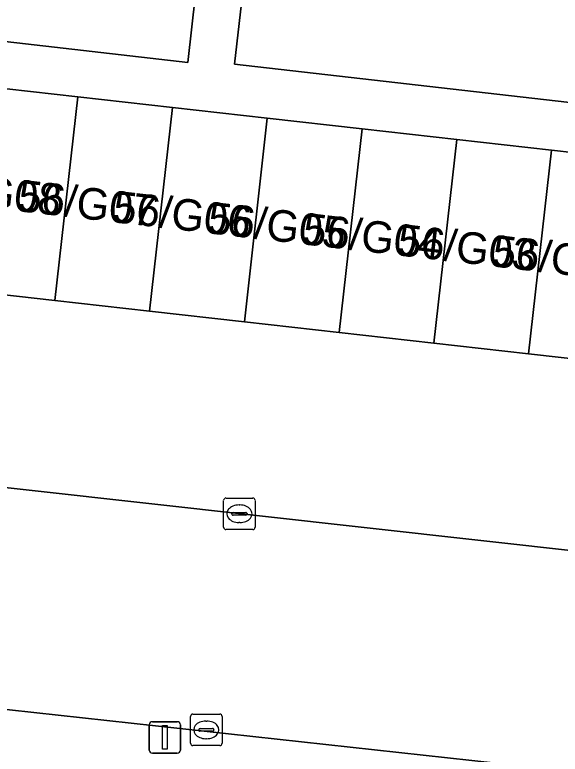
# Model space of a CAD drawing. Extents: x 161928 to 163071, y 386474 to 387428.
# Drawn here: x 162222.43 to 162239.74, y 386567.43 to 386590.88 of the extents above; entities that cross this region are included whole.
import ezdxf

# ---------------------------------------------------------------- set-up
doc = ezdxf.new("R2010")
doc.units = 0
for name, color, linetype in [('IMGEO_Erf', 7, 'Continuous'), ('IMGEO_Kolk', 7, 'Continuous'), ('IMGEO_Lichtmast', 7, 'Continuous'), ('IMGEO_Pand', 7, 'Continuous'), ('IMGEO_Pand_nummerreeks', 7, 'Continuous'), ('IMGEO_Rijbaan_lokaal_open', 7, 'Continuous'), ('IMGEO_Voetpad_open', 7, 'Continuous')]:
    doc.layers.add(name, color=color, linetype=linetype)

msp = doc.modelspace()

# ---------------------------------------------------------------- linework, layer by layer
at = {"layer": 'IMGEO_Erf'}
msp.add_lwpolyline([(162243.089, 386612.25), (162243.777, 386618.25), (162244.444, 386624.056), (162242.204, 386624.313), (162242.895, 386630.333), (162245.134, 386630.076), (162245.175, 386630.43), (162237.23, 386631.5), (162234.532, 386631.792), (162234.28, 386631.819), (162230.744, 386601.024), (162229.401, 386589.321), (162240.316, 386588.068), (162241.024, 386594.248), (162241.713, 386600.249), (162242.401, 386606.249)], close=True, dxfattribs=at)
msp.add_lwpolyline([(162222.049, 386626.7), (162221.352, 386620.648), (162220.657, 386614.617), (162219.964, 386608.612), (162219.27, 386602.591), (162218.588, 386596.675), (162217.88, 386590.526), (162227.916, 386589.37), (162228.16, 386591.548), (162225.844, 386591.807), (162226.29, 386595.787), (162226.733, 386599.742), (162229.232, 386599.462), (162229.7, 386603.636), (162227.201, 386603.916), (162227.633, 386607.77), (162228.08, 386611.753), (162230.578, 386611.473), (162231.038, 386615.572), (162228.598, 386615.846), (162229.038, 386619.772), (162229.484, 386623.756), (162231.925, 386623.482), (162232.4, 386627.717)], dxfattribs=at)
at = {"layer": 'IMGEO_Kolk'}
for p, q in [((162229.056, 386574.632), (162229.056, 386575.484)), ((162229.131, 386575.558), (162229.983, 386575.558)), ((162230.057, 386575.484), (162230.057, 386574.632)), ((162229.544, 386575.338), (162229.569, 386575.338)), ((162229.315, 386575.052), (162229.315, 386575.064)), ((162229.753, 386575.015), (162229.355, 386575.015)), ((162229.358, 386575.101), (162229.756, 386575.101)), ((162229.799, 386575.064), (162229.799, 386575.052)), ((162229.567, 386574.778), (162229.542, 386574.778)), ((162229.983, 386574.558), (162229.131, 386574.558)), ((162228.08, 386568.705), (162228.932, 386568.705)), ((162228.005, 386567.779), (162228.005, 386568.631)), ((162228.493, 386568.485), (162228.518, 386568.485)), ((162229.006, 386568.631), (162229.006, 386567.779)), ((162228.264, 386568.199), (162228.264, 386568.211)), ((162228.307, 386568.248), (162228.705, 386568.248)), ((162228.748, 386568.211), (162228.748, 386568.199)), ((162228.702, 386568.162), (162228.304, 386568.162)), ((162228.516, 386567.925), (162228.491, 386567.925)), ((162228.932, 386567.705), (162228.08, 386567.705))]:
    msp.add_line(p, q, dxfattribs=at)
for points in [[(162229.056, 386574.632), (162229.056, 386575.484)], [(162229.131, 386575.558), (162229.983, 386575.558)], [(162230.057, 386575.484), (162230.057, 386574.632)], [(162229.983, 386574.558), (162229.131, 386574.558)], [(162228.08, 386568.705), (162228.932, 386568.705)], [(162228.005, 386567.779), (162228.005, 386568.631)], [(162229.006, 386568.631), (162229.006, 386567.779)], [(162228.932, 386567.705), (162228.08, 386567.705)]]:
    msp.add_lwpolyline(points, dxfattribs=at)
for centre, radius, start, end in [((162229.133, 386575.482), 0.0765, 91.552, 178.448), ((162229.133, 386575.482), 0.0765, 91.552, 178.448), ((162229.981, 386575.482), 0.0765, 1.552, 88.448), ((162229.981, 386575.482), 0.0765, 1.552, 88.448), ((162229.355, 386575.061), 0.0403, 85.8775, 175.7526), ((162229.352, 386575.051), 0.0366, 178.938, 274.7102), ((162229.756, 386575.058), 0.043, 264.8664, 352.4533), ((162229.76, 386575.063), 0.0386, 1.7309, 96.639), ((162229.133, 386574.634), 0.0765, 181.552, 268.448), ((162229.133, 386574.634), 0.0765, 181.552, 268.448), ((162229.981, 386574.634), 0.0765, 271.552, 358.448), ((162229.981, 386574.634), 0.0765, 271.552, 358.448), ((162228.082, 386568.629), 0.0765, 91.552, 178.448), ((162228.082, 386568.629), 0.0765, 91.552, 178.448), ((162228.93, 386568.629), 0.0765, 1.552, 88.448), ((162228.93, 386568.629), 0.0765, 1.552, 88.448), ((162228.304, 386568.208), 0.0403, 85.8775, 175.7526), ((162228.709, 386568.21), 0.0386, 1.7309, 96.639), ((162228.301, 386568.198), 0.0366, 178.938, 274.7102), ((162228.705, 386568.205), 0.043, 264.8664, 352.4533), ((162228.082, 386567.781), 0.0765, 181.552, 268.448), ((162228.082, 386567.781), 0.0765, 181.552, 268.448), ((162228.93, 386567.781), 0.0765, 271.552, 358.448), ((162228.93, 386567.781), 0.0765, 271.552, 358.448)]:
    msp.add_arc(centre, radius, start, end, dxfattribs=at)
for centre, major_axis, ratio, start_param, end_param in [((162229.543, 386575.058), (-0.387, 0.002), 0.722429, 4.712389, 7.853982), ((162229.568, 386575.058), (-0.39, 0.002), 0.717154, 1.570796, 4.712389), ((162228.492, 386568.205), (-0.387, 0.002), 0.722429, 4.712389, 7.853982), ((162228.517, 386568.205), (-0.39, 0.002), 0.717154, 1.570796, 4.712389)]:
    msp.add_ellipse(centre, major_axis=major_axis, ratio=ratio, start_param=start_param, end_param=end_param, dxfattribs=at)
at = {"layer": 'IMGEO_Lichtmast'}
for p, q in [((162226.795, 386568.464), (162227.585, 386568.464)), ((162227.585, 386568.464), (162226.795, 386568.464)), ((162226.695, 386567.564), (162226.695, 386568.364)), ((162226.695, 386568.364), (162226.695, 386567.564)), ((162227.685, 386568.364), (162227.685, 386567.564)), ((162227.685, 386567.564), (162227.685, 386568.364)), ((162227.585, 386567.464), (162226.795, 386567.464)), ((162226.795, 386567.464), (162227.585, 386567.464))]:
    msp.add_line(p, q, dxfattribs=at)
msp.add_lwpolyline([(162227.115, 386568.339), (162227.265, 386568.339), (162227.265, 386567.589), (162227.115, 386567.589), (162227.115, 386568.339)], dxfattribs=at)
for centre, start, end in [((162226.795, 386568.364), 90, 180), ((162226.795, 386568.364), 90, 180), ((162227.585, 386568.364), 0, 90), ((162227.585, 386568.364), 360, 90), ((162226.795, 386567.564), 180, 270), ((162226.795, 386567.564), 180, 270), ((162227.585, 386567.564), 270, 0), ((162227.585, 386567.564), 270, 0)]:
    msp.add_arc(centre, 0.1, start, end, dxfattribs=at)
at = {"layer": 'IMGEO_Pand'}
for points in [[(162223.699, 386581.825), (162224.426, 386588.28), (162221.419, 386588.619), (162220.692, 386582.164)], [(162226.707, 386581.487), (162227.433, 386587.942), (162224.426, 386588.28), (162223.699, 386581.825)], [(162229.714, 386581.148), (162230.441, 386587.603), (162227.433, 386587.942), (162226.707, 386581.487)], [(162232.721, 386580.81), (162233.448, 386587.265), (162230.441, 386587.603), (162229.714, 386581.148)], [(162235.728, 386580.471), (162236.455, 386586.926), (162233.448, 386587.265), (162232.721, 386580.81)], [(162238.735, 386580.132), (162239.462, 386586.587), (162236.455, 386586.926), (162235.728, 386580.471)], [(162241.742, 386579.794), (162242.469, 386586.249), (162239.462, 386586.587), (162238.735, 386580.132)]]:
    msp.add_lwpolyline(points, close=True, dxfattribs=at)
at = {"layer": 'IMGEO_Rijbaan_lokaal_open'}
msp.add_lwpolyline([(162253.921, 386565.373), (162259.408, 386564.757), (162261.164, 386564.56), (162261.912, 386571.45), (162256.384, 386572.068), (162250.613, 386572.714), (162244.143, 386573.437), (162208.921, 386577.363), (162207.377, 386577.546), (162206.668, 386570.539), (162216.075, 386569.522)], close=True, dxfattribs=at)
at = {"layer": 'IMGEO_Voetpad_open'}
for points in [[(162240.316, 386588.068), (162229.401, 386589.321), (162230.744, 386601.024), (162234.28, 386631.819), (162234.532, 386631.792), (162237.23, 386631.5), (162245.175, 386630.43)], [(162204.829, 386592.006), (162204.672, 386590.589), (162212.398, 386589.635), (162215.405, 386589.296), (162218.412, 386588.958), (162221.419, 386588.619), (162224.426, 386588.28), (162227.433, 386587.942), (162230.441, 386587.603), (162233.448, 386587.265), (162236.455, 386586.926), (162239.462, 386586.587), (162242.469, 386586.249)], [(162228.16, 386591.548), (162227.916, 386589.37), (162217.88, 386590.526), (162214.92, 386590.867), (162209.952, 386591.44)], [(162208.921, 386577.363), (162244.143, 386573.437), (162244.508, 386576.484), (162244.749, 386579.455), (162241.742, 386579.794), (162238.735, 386580.132), (162235.728, 386580.471), (162232.721, 386580.81), (162229.714, 386581.148), (162226.707, 386581.487), (162223.699, 386581.825), (162220.692, 386582.164), (162217.685, 386582.503), (162214.678, 386582.841), (162211.671, 386583.18), (162211.429, 386580.799), (162211.241, 386579.068)], [(162264.757, 386564.157), (162261.164, 386564.56), (162259.408, 386564.757), (162259.352, 386564.248), (162253.864, 386564.861), (162253.921, 386565.373), (162216.075, 386569.522), (162206.668, 386570.539), (162206.218, 386567.564), (162215.553, 386566.525), (162228.384, 386565.127), (162229.979, 386564.953), (162250.594, 386562.706), (162253.622, 386562.454), (162258.523, 386561.805), (162261.299, 386561.458)]]:
    msp.add_lwpolyline(points, dxfattribs=at)

# ---------------------------------------------------------------- texts
at = {"layer": 'IMGEO_Pand_nummerreeks'}
for s, p in [('56/G08', (162219.487, 386585.013)), ('56/G07', (162222.495, 386584.663)), ('56/G06', (162225.506, 386584.313)), ('56/G05', (162228.518, 386583.962)), ('56/G04', (162231.529, 386583.612)), ('56/G03', (162234.54, 386583.262)), ('56/G02', (162237.546, 386582.912))]:
    msp.add_text(s, height=1, rotation=353.3634, dxfattribs=at).set_placement(p)

doc.saveas('drawing.dxf')
